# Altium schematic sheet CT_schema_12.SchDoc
size 209 x 185 mm
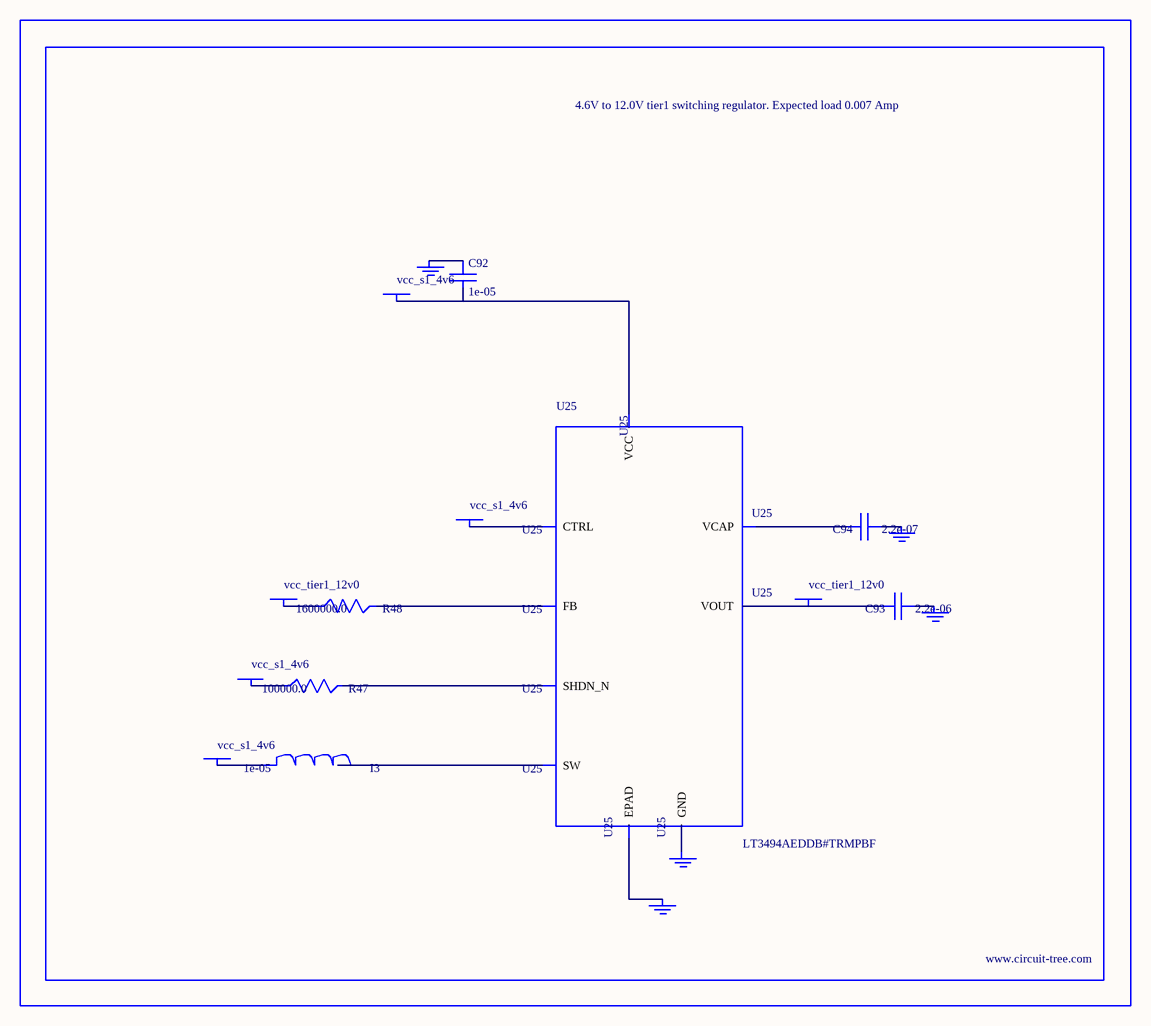
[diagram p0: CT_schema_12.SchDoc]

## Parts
BORDER11  (no value)
C92  1e-05  [C1210]
C93  2.2e-06  [C0603]
C94  2.2e-07  [C0603]
GND_INSTANCE_11_0  (no value)
GND_INSTANCE_11_1  (no value)
GND_INSTANCE_11_2  (no value)
GND_INSTANCE_11_3  (no value)
GND_INSTANCE_11_4  (no value)
I3  1e-05  [L1210]
POWER_INSTANCE_11_0  vcc_s1_4v6
POWER_INSTANCE_11_1  vcc_s1_4v6
POWER_INSTANCE_11_2  vcc_s1_4v6
POWER_INSTANCE_11_3  vcc_s1_4v6
POWER_INSTANCE_11_4  vcc_tier1_12v0
POWER_INSTANCE_11_5  vcc_tier1_12v0
R47  100000.0  [R0603]
R48  1600000.0  [R0603]
U25  LT3494AEDDB#TRMPBF  [DFN-8_DDB]

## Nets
NetC92_1: C92.1 GND_INSTANCE_11_0.0(GND)
NetC92_2: C92.2 POWER_INSTANCE_11_1.0(PWR) U25.3(VCC)
NetC93_1: C93.1 GND_INSTANCE_11_1.0(GND)
NetC93_2: C93.2 POWER_INSTANCE_11_5.0(PWR) U25.7(VOUT)
NetC94_1: C94.1 GND_INSTANCE_11_2.0(GND)
NetC94_2: C94.2 U25.8(VCAP)
NetGND_INSTANCE_11_3_0: GND_INSTANCE_11_3.0(GND) U25.9(EPAD)
NetGND_INSTANCE_11_4_0: GND_INSTANCE_11_4.0(GND) U25.2(GND)
NetI3_1: I3.1 POWER_INSTANCE_11_0.0(PWR)
NetI3_2: I3.2 U25.1(SW)
NetPOWER_INSTANCE_11_2_0: POWER_INSTANCE_11_2.0(PWR) U25.4(CTRL)
NetPOWER_INSTANCE_11_3_0: POWER_INSTANCE_11_3.0(PWR) R47.1
NetPOWER_INSTANCE_11_4_0: POWER_INSTANCE_11_4.0(PWR) R48.1
NetR47_2: R47.2 U25.5(SHDN_N)
NetR48_2: R48.2 U25.6(FB)

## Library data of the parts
BORDER11 = BORDER_PAGE11
C92 = C1210C106K5PACTU
C93 = GRM188R61H225KE1115D
C94 = C0603C224K3RAC
GND_INSTANCE_11_0-GND_INSTANCE_11_4 = GND
I3 = CBC3225T100MR
POWER_INSTANCE_11_0-POWER_INSTANCE_11_5 = PWR
R47 = RC0603JR-07100KL
R48 = RC0603JR-071M6L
